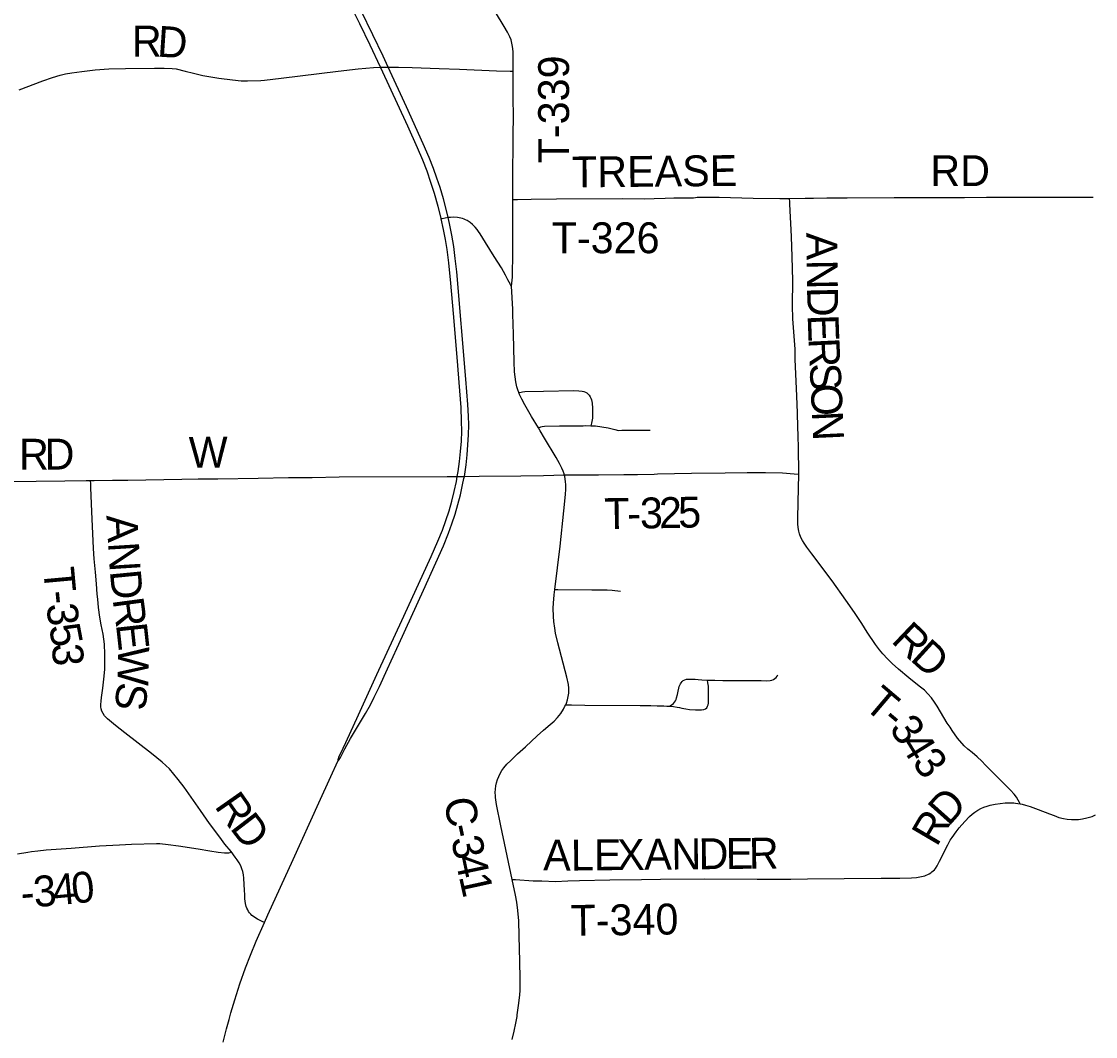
# Model space of a CAD drawing. Extents: x 40529 to 41139, y 15164 to 15584.
# Drawn here: x 40678.4 to 40737.8, y 15427.7 to 15483.8 of the extents above; entities that cross this region are included whole.
import ezdxf

# ---------------------------------------------------------------- set-up
doc = ezdxf.new("R2010")
doc.units = 0
for name, color, linetype in [('GM_X_County_Road', 7, 'Continuous'), ('GM_X_County_Road_Text', 7, 'Continuous'), ('GM_X_State_Route', 7, 'Continuous'), ('GM_X_Township_Road', 7, 'Continuous'), ('GM_X_Township_Road_Text', 7, 'Continuous')]:
    doc.layers.add(name, color=color, linetype=linetype)

msp = doc.modelspace()

# ---------------------------------------------------------------- linework, layer by layer
at = {"layer": 'GM_X_County_Road'}
for points in [[(40698.688, 15481.25), (40698.408, 15481.857), (40697.852, 15483.037), (40697.191, 15484.373)], [(40701.998, 15472.954), (40701.931, 15473.256), (40701.745, 15473.977), (40701.562, 15474.602), (40701.389, 15475.133), (40701.198, 15475.657), (40700.955, 15476.261), (40700.62, 15477.029), (40699.697, 15479.066), (40698.688, 15481.25)], [(40701.998, 15472.954), (40701.674, 15472.885), (40701.622, 15472.874)], [(40703.689, 15472.179), (40703.616, 15472.28), (40703.494, 15472.424), (40703.36, 15472.557), (40703.213, 15472.676), (40703.053, 15472.779), (40702.969, 15472.823), (40702.883, 15472.861), (40702.793, 15472.894), (40702.702, 15472.92), (40702.514, 15472.95), (40702.326, 15472.964), (40702.138, 15472.958), (40701.998, 15472.954)], [(40705.512, 15469.154), (40705.442, 15469.26), (40705.312, 15469.513), (40705.181, 15469.761), (40704.948, 15470.165), (40704.557, 15470.791), (40704.077, 15471.578), (40703.781, 15472.053), (40703.689, 15472.179)], [(40705.915, 15463.277), (40705.856, 15463.429), (40705.803, 15463.606), (40705.743, 15463.876), (40705.7, 15464.15), (40705.673, 15464.426), (40705.647, 15464.986), (40705.615, 15466.503), (40705.577, 15467.615), (40705.572, 15467.892), (40705.512, 15469.154)], [(40706.993, 15461.336), (40706.618, 15461.961), (40706.248, 15462.595), (40706.074, 15462.921), (40705.956, 15463.172), (40705.915, 15463.277)], [(40708.425, 15458.732), (40708.41, 15458.79), (40708.359, 15458.935), (40708.283, 15459.11), (40708.156, 15459.364), (40707.979, 15459.688), (40707.326, 15460.755), (40707.097, 15461.163), (40706.993, 15461.336)], [(40707.906, 15452.396), (40708.186, 15454.79), (40708.397, 15456.743), (40708.468, 15457.459), (40708.468, 15457.524), (40708.484, 15457.615), (40708.509, 15457.988), (40708.508, 15458.176), (40708.494, 15458.363), (40708.448, 15458.639), (40708.425, 15458.732)], [(40708.5, 15446.041), (40708.54, 15446.129), (40708.603, 15446.306), (40708.645, 15446.49), (40708.672, 15446.68), (40708.676, 15446.783), (40708.676, 15446.959), (40708.655, 15447.153), (40708.555, 15447.567), (40708.062, 15449.449), (40707.94, 15449.992), (40707.891, 15450.266), (40707.845, 15450.633), (40707.828, 15450.91), (40707.817, 15451.37), (40707.829, 15451.647), (40707.872, 15452.11), (40707.906, 15452.396)], [(40705.548, 15436.389), (40704.909, 15439.349), (40704.678, 15440.53), (40704.643, 15440.777), (40704.624, 15440.911), (40704.614, 15441), (40704.608, 15441.184), (40704.616, 15441.368), (40704.638, 15441.551), (40704.678, 15441.728), (40704.734, 15441.903), (40704.801, 15442.074), (40704.881, 15442.239), (40704.975, 15442.396), (40705.081, 15442.547), (40705.254, 15442.762), (40705.467, 15442.962), (40705.842, 15443.322), (40706.271, 15443.707), (40706.927, 15444.314), (40707.282, 15444.631), (40707.647, 15444.938), (40707.855, 15445.132), (40708.05, 15445.336), (40708.23, 15445.552), (40708.378, 15445.786), (40708.46, 15445.952), (40708.5, 15446.041)], [(40705.812, 15428.819), (40705.828, 15428.905), (40705.919, 15429.554), (40705.963, 15430.013), (40705.977, 15430.255), (40705.986, 15430.921), (40705.964, 15431.848), (40705.936, 15433.269), (40705.911, 15434.107), (40705.862, 15434.67), (40705.797, 15435.135), (40705.735, 15435.525), (40705.548, 15436.389)], [(40705.541, 15427.541), (40705.66, 15428), (40705.742, 15428.446), (40705.812, 15428.819)]]:
    msp.add_lwpolyline(points, dxfattribs=at)
at = {"layer": 'GM_X_State_Route'}
for points in [[(40695.917, 15442.927), (40695.922, 15442.965), (40695.934, 15443.015), (40695.954, 15443.074), (40695.974, 15443.132), (40696.213, 15443.638), (40696.348, 15443.951), (40697.051, 15445.486), (40698.063, 15447.705), (40699.564, 15450.922), (40701.066, 15454.227), (40701.439, 15455.081), (40701.684, 15455.686), (40701.878, 15456.211), (40702.053, 15456.742), (40702.208, 15457.28), (40702.343, 15457.823), (40702.459, 15458.37), (40702.509, 15458.65), (40702.557, 15458.921), (40702.636, 15459.475), (40702.694, 15460.032), (40702.734, 15460.59), (40702.754, 15461.15), (40702.752, 15461.71), (40702.722, 15462.456), (40702.659, 15463.386), (40702.496, 15465.243), (40702.3, 15467.657), (40702.152, 15469.328), (40702.038, 15470.44), (40701.945, 15471.18), (40701.858, 15471.733), (40701.754, 15472.283), (40701.622, 15472.874), (40701.612, 15472.92), (40701.453, 15473.553), (40701.25, 15474.271), (40701.053, 15474.894), (40700.837, 15475.51), (40700.601, 15476.12), (40700.309, 15476.806), (40699.774, 15477.996), (40698.289, 15481.211), (40698.269, 15481.255), (40697.695, 15482.476), (40697.124, 15483.649), (40696.496, 15484.899)], [(40698.688, 15481.25), (40698.408, 15481.857), (40697.852, 15483.037), (40697.191, 15484.373)], [(40701.998, 15472.954), (40701.931, 15473.256), (40701.745, 15473.977), (40701.562, 15474.602), (40701.389, 15475.133), (40701.198, 15475.657), (40700.955, 15476.261), (40700.62, 15477.029), (40699.697, 15479.066), (40698.688, 15481.25)], [(40698.658, 15448.027), (40698.859, 15448.462), (40699.286, 15449.392), (40700.638, 15452.357), (40701.332, 15453.882), (40701.74, 15454.82), (40702.02, 15455.51), (40702.212, 15456.033), (40702.386, 15456.562), (40702.542, 15457.098), (40702.681, 15457.638), (40702.803, 15458.182), (40702.878, 15458.54), (40702.903, 15458.654), (40702.992, 15459.281), (40703.057, 15459.835), (40703.102, 15460.391), (40703.13, 15460.949), (40703.141, 15461.507), (40703.133, 15461.972), (40703.098, 15462.622), (40702.988, 15464.015), (40702.478, 15469.955), (40702.402, 15470.696), (40702.314, 15471.341), (40702.204, 15471.983), (40702.076, 15472.621), (40701.998, 15472.954)], [(40695.917, 15442.927), (40695.952, 15442.965), (40695.992, 15443.02), (40696.019, 15443.066), (40696.052, 15443.122), (40696.294, 15443.603), (40696.611, 15444.178), (40696.997, 15444.823), (40697.431, 15445.548), (40697.707, 15446.039), (40697.924, 15446.455), (40698.207, 15447.048), (40698.658, 15448.027)], [(40689.897, 15428.659), (40689.997, 15429.027), (40690.211, 15429.741), (40690.502, 15430.627), (40690.812, 15431.506), (40691.079, 15432.202), (40691.4, 15432.977), (40691.851, 15434.004), (40692.037, 15434.429), (40693.433, 15437.483), (40694.866, 15440.624), (40695.523, 15442.066), (40695.917, 15442.927)], [(40689.572, 15427.404), (40689.753, 15428.127), (40689.897, 15428.659)]]:
    msp.add_lwpolyline(points, dxfattribs=at)
at = {"layer": 'GM_X_Township_Road'}
for p, q in [((40702.509, 15458.65), (40702.696, 15458.652)), ((40702.696, 15458.652), (40702.903, 15458.654))]:
    msp.add_line(p, q, dxfattribs=at)
for points in [[(40705.597, 15481.033), (40705.599, 15481.746), (40705.591, 15482.12), (40705.564, 15482.399), (40705.511, 15482.673), (40705.483, 15482.762), (40705.416, 15482.936), (40705.292, 15483.186), (40705.105, 15483.508), (40704.615, 15484.295)], [(40678.305, 15480.007), (40679.613, 15480.497), (40680.135, 15480.687), (40680.56, 15480.815), (40680.86, 15480.889), (40681.217, 15480.948), (40681.77, 15481.024), (40682.51, 15481.1), (40683.249, 15481.156), (40684.171, 15481.18), (40685.774, 15481.195), (40686.307, 15481.203), (40686.756, 15481.19), (40686.968, 15481.156), (40687.481, 15481.037), (40687.93, 15480.924), (40688.458, 15480.801), (40689.341, 15480.648), (40690.081, 15480.549), (40690.564, 15480.505), (40690.91, 15480.495), (40691.664, 15480.519), (40691.849, 15480.535), (40692.777, 15480.642), (40695.925, 15481.036), (40697.037, 15481.162), (40697.872, 15481.236), (40698.244, 15481.255), (40698.269, 15481.255)], [(40698.269, 15481.255), (40698.617, 15481.25), (40698.688, 15481.25), (40699.268, 15481.249), (40700.014, 15481.24), (40701.506, 15481.185), (40702.626, 15481.139), (40704.678, 15481.062), (40705.425, 15481.039), (40705.597, 15481.033)], [(40705.587, 15473.951), (40705.587, 15475.602), (40705.6, 15476.812), (40705.599, 15477.464), (40705.608, 15478.582), (40705.597, 15479.514), (40705.595, 15480.258), (40705.597, 15481.033)], [(40705.512, 15469.154), (40705.563, 15469.658), (40705.564, 15469.937), (40705.586, 15470.772), (40705.586, 15472.718), (40705.587, 15473.951)], [(40705.587, 15473.951), (40705.751, 15473.949), (40705.845, 15473.948), (40706.592, 15473.957), (40707.985, 15473.978), (40711.636, 15473.998), (40712.833, 15473.982), (40713.397, 15473.996), (40714.004, 15474.012), (40714.468, 15474.032), (40715.568, 15474.044), (40715.671, 15474.061), (40715.766, 15474.07), (40715.953, 15474.073), (40716.981, 15474.069), (40718.851, 15474.028), (40720.34, 15474.007), (40720.804, 15474.004), (40720.874, 15474.005)], [(40720.874, 15474.005), (40721.729, 15474.011), (40722.194, 15474.024), (40722.934, 15474.045), (40724.044, 15474.034), (40726.649, 15474.052), (40728.97, 15474.055), (40730.536, 15474.066), (40731.749, 15474.077), (40735.291, 15474.077), (40737.651, 15474.067)], [(40721.38, 15458.768), (40721.38, 15458.79), (40721.369, 15460.276), (40721.352, 15460.831), (40721.306, 15462.077), (40721.309, 15462.159), (40721.277, 15463.083), (40721.187, 15465.123), (40721.171, 15465.68), (40721.058, 15467.358), (40721.034, 15468.093), (40721.042, 15469.477), (40721.014, 15470.78), (40720.982, 15471.894), (40720.886, 15473.687), (40720.881, 15473.825), (40720.874, 15474.005)], [(40705.915, 15463.277), (40706.04, 15463.309), (40706.119, 15463.33), (40706.251, 15463.337), (40707.274, 15463.367), (40708.946, 15463.387), (40709.232, 15463.369), (40709.408, 15463.355), (40709.498, 15463.335), (40709.586, 15463.303), (40709.667, 15463.26), (40709.738, 15463.202), (40709.796, 15463.129), (40709.844, 15463.05), (40709.885, 15462.967), (40709.917, 15462.88), (40709.941, 15462.791), (40709.959, 15462.7), (40709.971, 15462.608), (40709.977, 15462.515), (40709.976, 15462.329), (40709.983, 15462.05), (40709.981, 15461.865), (40709.971, 15461.774), (40709.953, 15461.683), (40709.925, 15461.598), (40709.886, 15461.453)], [(40706.993, 15461.336), (40707.125, 15461.38), (40707.199, 15461.405), (40707.32, 15461.418), (40708.157, 15461.445), (40709.005, 15461.449), (40709.469, 15461.449), (40709.622, 15461.454), (40709.886, 15461.453)], [(40709.886, 15461.453), (40710.154, 15461.44), (40710.85, 15461.341), (40711.216, 15461.246)], [(40711.216, 15461.246), (40711.422, 15461.193), (40711.605, 15461.198), (40712.425, 15461.206), (40712.798, 15461.202), (40713.173, 15461.213)], [(40682.252, 15458.425), (40682.44, 15458.428), (40683.46, 15458.438), (40683.835, 15458.438), (40684.302, 15458.448), (40687.284, 15458.496), (40688.197, 15458.512), (40689.276, 15458.521), (40691.515, 15458.562), (40693.193, 15458.586), (40694.498, 15458.597), (40695.988, 15458.619), (40701.95, 15458.644), (40702.509, 15458.65)], [(40702.903, 15458.654), (40703.719, 15458.664), (40706.03, 15458.684), (40707.279, 15458.708), (40708.425, 15458.732)], [(40708.425, 15458.732), (40708.739, 15458.733), (40710.322, 15458.738), (40711.721, 15458.761), (40712.465, 15458.762), (40713.394, 15458.777), (40713.577, 15458.786), (40715.444, 15458.824), (40717.313, 15458.856), (40718.522, 15458.862), (40719.546, 15458.861), (40720.481, 15458.841), (40721.13, 15458.797), (40721.38, 15458.768)], [(40733.61, 15440.559), (40733.573, 15440.632), (40733.509, 15440.761), (40733.403, 15440.925), (40733.277, 15441.096), (40733.074, 15441.31), (40732.82, 15441.583), (40732.222, 15442.167), (40731.701, 15442.701), (40731.487, 15442.921), (40731.235, 15443.163), (40730.959, 15443.4), (40730.727, 15443.578), (40730.52, 15443.77), (40730.155, 15444.199), (40729.859, 15444.618), (40729.745, 15444.796), (40729.582, 15445.028), (40729.018, 15445.958), (40728.882, 15446.177), (40728.704, 15446.414), (40728.512, 15446.636), (40728.324, 15446.833), (40728.033, 15447.065), (40727.46, 15447.525), (40726.886, 15447.998), (40726.541, 15448.308), (40726.277, 15448.571), (40726.025, 15448.845), (40725.848, 15449.061), (40725.625, 15449.36), (40725.156, 15450.052), (40724.857, 15450.52), (40724.451, 15451.136), (40723.981, 15451.821), (40723.232, 15452.882), (40722.099, 15454.366), (40721.829, 15454.745), (40721.673, 15454.965), (40721.585, 15455.116), (40721.502, 15455.269), (40721.428, 15455.476), (40721.388, 15455.629), (40721.349, 15455.827), (40721.328, 15456.024), (40721.328, 15456.351), (40721.354, 15457.216), (40721.38, 15458.768)], [(40675.645, 15458.343), (40675.674, 15458.344), (40675.886, 15458.345), (40677.657, 15458.374), (40680.824, 15458.401), (40681.998, 15458.42), (40682.252, 15458.425)], [(40690.011, 15437.922), (40689.665, 15438.344), (40689.392, 15438.731), (40688.823, 15439.47), (40688.33, 15440.191), (40688.06, 15440.558), (40687.414, 15441.475), (40687.087, 15441.916), (40686.851, 15442.21), (40686.603, 15442.489), (40686.406, 15442.688), (40686.198, 15442.872), (40685.616, 15443.338), (40684.138, 15444.482), (40683.619, 15444.886), (40683.288, 15445.167), (40683.19, 15445.256), (40683.111, 15445.325), (40683.022, 15445.423), (40682.938, 15445.552), (40682.874, 15445.675), (40682.834, 15445.818), (40682.815, 15445.927), (40682.81, 15446.05), (40682.825, 15446.237), (40682.854, 15446.44), (40682.933, 15446.948), (40683.007, 15447.619), (40683.032, 15447.999), (40683.037, 15448.359), (40683.032, 15448.827), (40683.016, 15449.388), (40682.941, 15449.939), (40682.829, 15450.46), (40682.755, 15450.875), (40682.686, 15451.407), (40682.64, 15451.871), (40682.617, 15452.151), (40682.583, 15452.709), (40682.512, 15453.358), (40682.45, 15454.103), (40682.416, 15454.663), (40682.323, 15456.711), (40682.263, 15458.02), (40682.257, 15458.249), (40682.252, 15458.425)], [(40707.906, 15452.396), (40708.075, 15452.395), (40709.948, 15452.385), (40710.792, 15452.377), (40711.073, 15452.364), (40711.536, 15452.314)], [(40714.237, 15445.957), (40714.38, 15446.042), (40714.463, 15446.106), (40714.518, 15446.175), (40714.562, 15446.25), (40714.6, 15446.331), (40714.632, 15446.416), (40714.681, 15446.595), (40714.715, 15446.78), (40714.757, 15446.957), (40714.776, 15447.037), (40714.806, 15447.121), (40714.835, 15447.19), (40714.875, 15447.254), (40714.929, 15447.313), (40714.998, 15447.368), (40715.092, 15447.417), (40715.181, 15447.447), (40715.259, 15447.456), (40715.467, 15447.456), (40715.654, 15447.447), (40715.827, 15447.432), (40716.024, 15447.417), (40716.342, 15447.401)], [(40714.237, 15445.957), (40714.465, 15445.942), (40714.662, 15445.907), (40714.786, 15445.878), (40714.919, 15445.848), (40715.136, 15445.804), (40715.343, 15445.774), (40715.669, 15445.755), (40716.004, 15445.76), (40716.133, 15445.769), (40716.231, 15445.804), (40716.298, 15445.872), (40716.341, 15445.952), (40716.365, 15446.041), (40716.382, 15446.131), (40716.393, 15446.222), (40716.399, 15446.41), (40716.399, 15446.692), (40716.4, 15446.877), (40716.389, 15447.063), (40716.363, 15447.245), (40716.342, 15447.401)], [(40716.342, 15447.401), (40716.404, 15447.397), (40716.749, 15447.387), (40717.178, 15447.382), (40717.77, 15447.373), (40718.466, 15447.368), (40718.678, 15447.368), (40718.861, 15447.368), (40719.073, 15447.368), (40719.295, 15447.368), (40719.62, 15447.363), (40719.798, 15447.378), (40719.892, 15447.392), (40719.985, 15447.427), (40720.064, 15447.481), (40720.127, 15447.544), (40720.187, 15447.613), (40720.231, 15447.695)], [(40708.5, 15446.041), (40708.827, 15446.035), (40709.564, 15446.02), (40712.62, 15446.001), (40713.197, 15445.991), (40713.557, 15445.981), (40713.71, 15445.972), (40713.926, 15445.968), (40714.08, 15445.962), (40714.237, 15445.957)], [(40705.548, 15436.389), (40705.719, 15436.378), (40706.71, 15436.316), (40707.187, 15436.302), (40707.936, 15436.281), (40708.621, 15436.301), (40709.257, 15436.329), (40710.931, 15436.356), (40712.695, 15436.383), (40713.737, 15436.4), (40716.159, 15436.415), (40719.077, 15436.396), (40720.663, 15436.404), (40720.938, 15436.406), (40721.865, 15436.422), (40723.884, 15436.439), (40725.935, 15436.453), (40726.961, 15436.459), (40727.611, 15436.477), (40727.888, 15436.501), (40728.162, 15436.543), (40728.341, 15436.586), (40728.427, 15436.615), (40728.511, 15436.651), (40728.591, 15436.694), (40728.667, 15436.743), (40728.74, 15436.798), (40728.808, 15436.858), (40728.872, 15436.924), (40728.931, 15436.993), (40729.032, 15437.145), (40729.164, 15437.389), (40729.615, 15438.305), (40729.748, 15438.551), (40729.846, 15438.711), (40730.067, 15439.016), (40730.242, 15439.236), (40730.55, 15439.596), (40730.819, 15439.869), (40730.959, 15439.996), (40731.112, 15440.109), (40731.268, 15440.21), (40731.432, 15440.3), (40731.603, 15440.378), (40731.782, 15440.439), (40731.962, 15440.487), (40732.235, 15440.541), (40732.511, 15440.583), (40732.79, 15440.611), (40732.978, 15440.619), (40733.26, 15440.613), (40733.353, 15440.605), (40733.61, 15440.559)], [(40733.61, 15440.559), (40733.719, 15440.539), (40733.9, 15440.493), (40734.168, 15440.409), (40734.61, 15440.244), (40735.224, 15440.003), (40735.489, 15439.91), (40735.744, 15439.814), (40736.015, 15439.744), (40736.218, 15439.71), (40736.454, 15439.7), (40736.597, 15439.7), (40736.839, 15439.705), (40737.051, 15439.735), (40737.293, 15439.784), (40737.451, 15439.828), (40737.584, 15439.868), (40737.697, 15439.912), (40737.776, 15439.963)], [(40678.203, 15437.809), (40678.787, 15437.895), (40678.991, 15437.923), (40679.339, 15437.974), (40679.8, 15438.02), (40680.343, 15438.066), (40681.173, 15438.12), (40682.742, 15438.235), (40683.852, 15438.307), (40684.5, 15438.335), (40685.894, 15438.368), (40686.08, 15438.368), (40686.536, 15438.323), (40687.099, 15438.251), (40688.192, 15438.07), (40688.835, 15437.958), (40689.291, 15437.898), (40689.644, 15437.857), (40689.789, 15437.854), (40689.889, 15437.859), (40689.958, 15437.881), (40690.011, 15437.922)], [(40691.851, 15434.004), (40691.727, 15434.064), (40691.476, 15434.186), (40691.315, 15434.285), (40691.246, 15434.334), (40691.167, 15434.403), (40691.098, 15434.467), (40691.034, 15434.541), (40690.979, 15434.61), (40690.93, 15434.699), (40690.886, 15434.793), (40690.851, 15434.891), (40690.802, 15435.064), (40690.772, 15435.32), (40690.762, 15435.537), (40690.757, 15435.794), (40690.743, 15436.1), (40690.723, 15436.455), (40690.703, 15436.647), (40690.664, 15436.82), (40690.609, 15436.968), (40690.545, 15437.146), (40690.461, 15437.308), (40690.353, 15437.461), (40690.239, 15437.614), (40690.011, 15437.922)]]:
    msp.add_lwpolyline(points, dxfattribs=at)

# ---------------------------------------------------------------- texts
at = {"layer": 'GM_X_County_Road_Text'}
for s, rotation, p in [('C', 278.24823, (40701.789, 15440.818)), ('-', 281.97936, (40702.011, 15439.311)), ('3', 281.8876, (40702.157, 15438.626)), ('4', 281.92243, (40702.373, 15437.597)), ('1', 282.40906, (40702.594, 15436.553))]:
    msp.add_text(s, height=1.706, rotation=rotation, dxfattribs=at).set_placement(p)
at = {"layer": 'GM_X_Township_Road_Text'}
for s, height, rotation, p in [('R', 1.706, 359.95316, (40684.528, 15481.845)), ('D', 1.706, 356.18689, (40685.9, 15481.845)), ('T-339', 1.7063, 90, (40708.686, 15475.943)), ('TREASE', 1.7063, 0.53418, (40708.857, 15474.612)), ('RD', 1.7063, 0.00001, (40728.648, 15474.687)), ('T-326', 1.7063, 0.00001, (40707.727, 15470.979)), ('A', 1.706, 270.90707, (40721.787, 15472.114)), ('N', 1.706, 270.90707, (40721.81, 15470.612)), ('D', 1.706, 271.19044, (40721.834, 15469.102)), ('E', 1.706, 272.06196, (40721.866, 15467.572)), ('R', 1.706, 272.65717, (40721.913, 15466.277)), ('S', 1.706, 272.69994, (40721.978, 15464.876)), ('O', 1.706, 272.70036, (40722.032, 15463.726)), ('N', 1.706, 272.70033, (40722.103, 15462.226)), ('W', 1.706, 0.72692, (40687.687, 15459.121)), ('R', 1.706, 0.00781, (40678.297, 15459.021)), ('D', 1.706, 0.53388, (40679.715, 15459.021)), ('T', 1.706, 0.87857, (40710.637, 15455.739)), ('3', 1.706, 0.92505, (40712.615, 15455.769)), ('2', 1.706, 1.05575, (40713.67, 15455.787)), ('5', 1.706, 1.47025, (40714.735, 15455.806)), ('A', 1.706, 273.39342, (40683.121, 15456.488)), ('-', 1.706, 0.88831, (40711.913, 15455.759)), ('N', 1.706, 273.5742, (40683.211, 15454.983)), ('T', 1.706, 275.26156, (40679.626, 15453.563)), ('D', 1.706, 275.52983, (40683.309, 15453.421)), ('-', 1.706, 275.33102, (40679.743, 15452.29)), ('3', 1.706, 275.60811, (40679.809, 15451.583)), ('R', 1.706, 277.6281, (40683.462, 15451.859)), ('5', 1.706, 280.72463, (40679.935, 15450.373)), ('E', 1.706, 276.31275, (40683.647, 15450.48)), ('R', 1.706, 316.38279, (40726.434, 15449.526)), ('D', 1.706, 317.66233, (40727.479, 15448.531)), ('3', 1.706, 272.29041, (40680.123, 15449.406)), ('W', 1.706, 268.46985, (40683.784, 15449.273)), ('S', 1.706, 263.79202, (40683.734, 15447.334)), ('T', 1.706, 319.67808, (40724.905, 15445.907)), ('-', 1.706, 319.66372, (40725.878, 15445.081)), ('3', 1.706, 305.11907, (40726.335, 15444.712)), ('4', 1.706, 301.80184, (40726.926, 15443.874)), ('3', 1.706, 307.72427, (40727.589, 15442.822)), ('R', 1.706, 305.04222, (40689.057, 15440.429)), ('D', 1.706, 48.23183, (40729.657, 15439.28)), ('D', 1.706, 307.50288, (40689.908, 15439.218)), ('R', 1.706, 59.56235, (40729, 15438.143)), ('A', 1.706, 359.4208, (40707.255, 15436.892)), ('L', 1.706, 0.52928, (40708.792, 15436.877)), ('E', 1.706, 0.58223, (40710.07, 15436.889)), ('X', 1.706, 0.58946, (40711.347, 15436.902)), ('A', 1.706, 0.58649, (40712.848, 15436.917)), ('N', 1.706, 0.58649, (40714.349, 15436.933)), ('D', 1.706, 0.58649, (40715.851, 15436.948)), ('E', 1.706, 0.58629, (40717.352, 15436.963)), ('R', 1.706, 0.58812, (40718.629, 15436.976)), ('3', 1.706, 5.11021, (40679.163, 15434.848)), ('4', 1.706, 5.48253, (40680.222, 15434.943)), ('0', 1.706, 5.60371, (40681.272, 15435.044)), ('-', 1.706, 4.6152, (40678.449, 15434.79)), ('T-340', 1.7063, 0.82603, (40708.78, 15433.266))]:
    msp.add_text(s, height=height, rotation=rotation, dxfattribs=at).set_placement(p)

doc.saveas('drawing.dxf')
